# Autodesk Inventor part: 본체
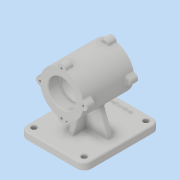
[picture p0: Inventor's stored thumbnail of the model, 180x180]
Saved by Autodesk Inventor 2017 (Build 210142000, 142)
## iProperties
Part Number: 본체
Material: 일반
Document SubType Name: Modeling
Designer: MRC
Density: 1 g/cm^3
Appearance: 기본값
Author: MRC
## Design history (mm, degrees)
sketch "스케치1"
  geometry: C1 r 37 at (0, 0); 1 further point
  constraints: 1 centre point, 1 coincident
  dimensions: "d0" = 74 diameter of C1
extrude "돌출1" new body sketch "스케치1" stored distance "d1" = 87; taper "d2" = 0 deg
sketch "스케치2"
  geometry: C1 r 23.5 at (0, 0); 1 further point
  constraints: 1 centre point, 1 coincident
  dimensions: "d3" = 47 diameter of C1
extrude "돌출2" cut sketch "스케치2" distance "d4" = 19; taper "d5" = 0 deg
sketch "스케치3"
  geometry: C1 r 23.5 at (0, 0); 1 further point
  constraints: 1 centre point, 1 coincident
  dimensions: "d6" = 47 diameter of C1
extrude "돌출3" cut sketch "스케치3" distance "d7" = 19; taper "d8" = 0 deg
sketch "스케치4"
  geometry: C1 r 21 at (0, 0); 1 further point
  constraints: 1 centre point, 1 coincident
  dimensions: "d9" = 42 diameter of C1
extrude "돌출4" cut sketch "스케치4" stored distance "d10" = 19; taper "d11" = 0 deg
fillet "모깎기1" dims "d12" = 1
chamfer "모따기1" distance "d13" = 1; stored, may be unused: second distance "d14" = 2, angle "d15" = 45 deg
sketch "스케치5"
  geometry: C1 r 7 at (0, 37); 2 further points
  constraints: 2 vertical alignment, 1 centre point, 1 other
  dimensions: "d16" = 14 diameter of C1
extrude "돌출5" join sketch "스케치5" distance "d17" = 14; taper "d18" = 0 deg
hole "구멍1" diameter "d21" = 3.242; stored, may be unused: countersink angle "d25" = 90 deg, drill point angle "d27" = 118 deg; dims "d19" = 10, "d20" = 10, "d22" = 8, "d23" = 4, "d24" = 2, "d26" = 10
fillet "모깎기2" dims "d31" = 3
fillet "모깎기3" dims "d32" = 3
sketch "스케치6"
  geometry: L1 (-70, 60)-(-82, 60); L2 (-82, 60)-(-82, -70); L3 (-82, -70)-(-70, -70); L4 (-70, -70)-(-70, 60); 1 further point
  constraints: 8 end point, 2 parallel, 1 horizontal, 1 perpendicular
  dimensions: "d33" = 82 distance from line of L2 point (0, 0); "d34" = 12 distance of L2.end L3.end; "d36" = 130 distance of L1.end L2.end; "d37" = 70 distance from line of L3 point (0, 0)
extrude "돌출6" join sketch "스케치6" stored distance "d38" = 110; taper "d39" = 0 deg
fillet "모깎기4" dims "d40" = 12
sketch "스케치7"
  geometry: C1 r 4.5 at (0, 118); C2 r 4.5 at (0, 12); C3 r 4.5 at (86, 12); C4 r 4.5 at (86, 118); A1 r 12 centre (0, 118) between (0, 130) and (-12, 118) reference; A2 r 12 centre (86, 118) between (98, 118) and (86, 130) reference; A3 r 12 centre (86, 12) between (86, 0) and (98, 12) reference; A4 r 12 centre (0, 12) between (-12, 12) and (0, 0) reference; 1 further point
  constraints: 4 centre point, 4 concentric
  dimensions: "d41" = 9 diameter of C1; "d42" = 9 diameter of C2; "d43" = 9 diameter of C3; "d44" = 9 diameter of C4
extrude "돌출7" cut sketch "스케치7" stored distance "d45" = 110; taper "d46" = 0 deg
sketch "스케치8"
  geometry: L1 (-41, -70)-(-28.854, -36.63); L2 (-43, -70)-(43, -70) reference; L3 (-55, -70)-(-55, -82) reference; L4 (-47.5, -70)-(-38.5, -70) reference; 1 further point
  constraints: 2 end point, 1 point on line
  dimensions: "d47" = 14 distance from line of L3 L1.start; "d48" = 110 deg angle of L4 L1
sketch "스케치9"
  geometry: C1 r 5 at (43, 60); 1 further point
  constraints: 1 centre point, 1 coincident
  dimensions: "d49" = 10 diameter of C1
extrude "돌출8" join sketch "스케치9" stored distance "d50" = 110; taper "d51" = 0 deg
feature "리브1" dims "d52" = 1, "d53" = 10, "d54" = 0, "d55" = 0, "d56" = 1, "d57" = 1
sketch "스케치10"
  geometry: L1 (-70, 30)-(-42.679, 20.056); L2 (-70, -58)-(-70, 48) reference; 1 further point
  constraints: 2 end point, 1 point on line
  dimensions: "d58" = 30 vertical distance of L1.start point (0, 0); "d59" = 110 deg angle of L2 L1
feature "리브2" sketch "스케치10" dims "d60" = 1, "d61" = 10, "d62" = 0, "d63" = 0, "d64" = 1, "d65" = 1
fillet "모깎기5" dims "d66" = 3
fillet "모깎기6" dims "d67" = 3
fillet "모깎기7" dims "d68" = 3
sketch "스케치11"
  geometry: 2 further points
  constraints: 1 vertical alignment, 1 other
  dimensions: "d71" = 58 distance of point (43, 57) point (43, 115)
feature "엠보싱1" sketch "스케치11" dims "d2" = 0, "d69" = 0.5, "d70" = 0
node "솔리드1"
pattern_circular "원형 패턴1" dims angle "d29" = 360 deg
mirror "미러1"
mirror "미러2"
mirror "미러3"
